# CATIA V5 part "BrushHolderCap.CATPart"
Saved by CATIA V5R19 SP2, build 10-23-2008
Part number: BrushHolderCap
Revision: ANY
Definition: UNKNOWN
Nomenclature: BrushHolderCap
Source: Unknown
Bounding box of the stored display mesh (mm): x -6 to 6, y 0 to 6, z -6 to 6
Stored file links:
  Z:\fausse table rondelle-20220905T211342Z-001\fausse table rondelle\BrushHolderCap.CATPart
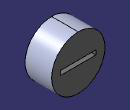
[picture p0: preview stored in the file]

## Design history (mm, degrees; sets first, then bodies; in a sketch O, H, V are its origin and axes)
AxisSystem1: origin (0, 0, 0), X (1, 0, 0), Y (0, 1, 0), Z (0, 0, 1)
Body1 "Schnitt-Linear austragen2" (main body)
  Solid1: solid without history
